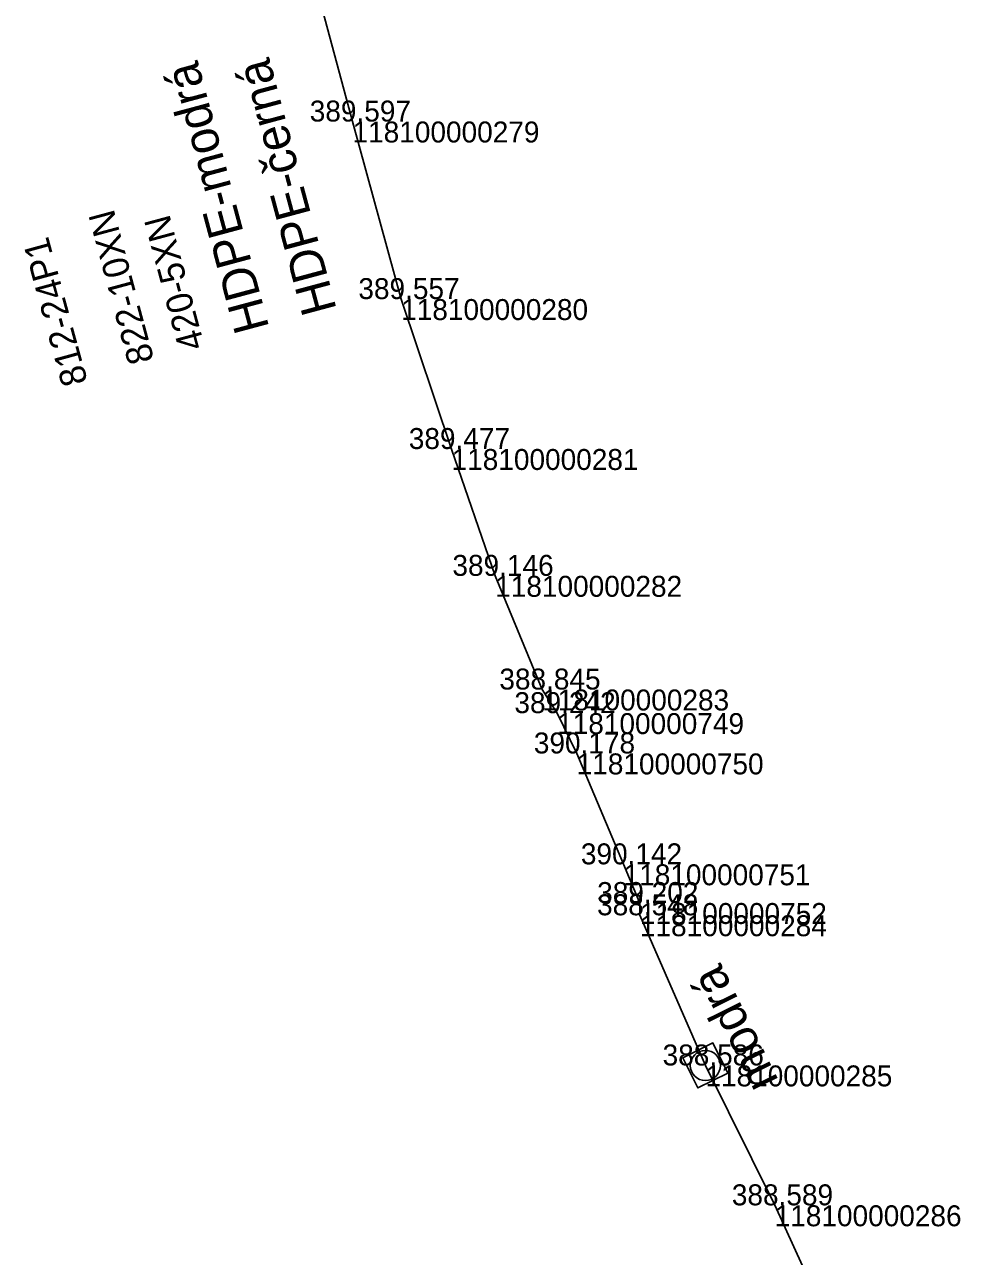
# Model space of a CAD drawing. Extents: x -724084 to -720954, y -948423 to -945131.
# Drawn here: x -721947.4 to -721893.7, y -947598.7 to -947528.1 of the extents above; entities that cross this region are included whole.
import ezdxf

# ---------------------------------------------------------------- set-up
doc = ezdxf.new("R2010")
doc.units = 0
for name, color, linetype in [('Vrstva 28', 7, 'Continuous'), ('Vrstva 31', 7, 'Continuous'), ('Vrstva 33', 7, 'Continuous'), ('Vrstva 60', 7, 'Continuous'), ('Vrstva 61', 7, 'Continuous')]:
    doc.layers.add(name, color=color, linetype=linetype)

msp = doc.modelspace()

# ---------------------------------------------------------------- linework, layer by layer
at = {"layer": 'Vrstva 28'}
for points in [[(-721916.845, -947567.574), (-721917.7, -947566.221), (-721920.393, -947559.707), (-721922.892, -947552.44), (-721925.781, -947543.85), (-721928.567, -947533.677), (-721931.184, -947523.941), (-721933.084, -947514.601), (-721934.922, -947507.209), (-721935.577, -947505.11), (-721937.863, -947494.901), (-721938.161, -947492.286)], [(-721916.845, -947567.574), (-721915.725, -947569.883), (-721913.037, -947576.236), (-721912.103, -947578.454)], [(-721901.7, -947601.624), (-721904.382, -947595.773), (-721908.35, -947587.759), (-721912.103, -947579.155), (-721912.103, -947578.454)]]:
    msp.add_lwpolyline(points, dxfattribs=at)
at = {"layer": 'Vrstva 31'}
for points in [[(-721916.845, -947567.574), (-721917.7, -947566.221), (-721920.393, -947559.707), (-721922.892, -947552.44), (-721925.781, -947543.85), (-721928.567, -947533.677), (-721931.184, -947523.941), (-721933.084, -947514.601), (-721934.922, -947507.209), (-721935.577, -947505.11), (-721937.863, -947494.901), (-721938.161, -947492.286)], [(-721912.103, -947578.454), (-721913.037, -947576.236), (-721915.725, -947569.883), (-721916.845, -947567.574)], [(-721901.7, -947601.624), (-721904.382, -947595.773), (-721908.35, -947587.759), (-721912.103, -947579.155), (-721912.103, -947578.454)]]:
    msp.add_lwpolyline(points, dxfattribs=at)
at = {"layer": 'Vrstva 33'}
msp.add_lwpolyline([(-721901.7, -947601.624), (-721904.382, -947595.773), (-721908.35, -947587.759), (-721912.103, -947579.155), (-721912.103, -947578.454), (-721913.037, -947576.236), (-721915.725, -947569.883), (-721916.845, -947567.574), (-721917.7, -947566.221), (-721920.393, -947559.707), (-721922.892, -947552.44), (-721925.781, -947543.85), (-721928.567, -947533.677), (-721931.184, -947523.941)], dxfattribs=at)
msp.add_lwpolyline([(-721907.064, -947588.193), (-721907.916, -947586.473), (-721909.636, -947587.325), (-721908.784, -947589.045)], close=True, dxfattribs=at)
msp.add_circle((-721908.35, -947587.759), 0.864, dxfattribs=at)
at = {"layer": 'Vrstva 60'}
for p, q in [((-721928.567, -947533.677), (-721928.567, -947533.677)), ((-721925.781, -947543.85), (-721925.781, -947543.85)), ((-721922.892, -947552.44), (-721922.892, -947552.44)), ((-721920.393, -947559.707), (-721920.393, -947559.707)), ((-721917.7, -947566.221), (-721917.7, -947566.221)), ((-721916.845, -947567.574), (-721916.845, -947567.574)), ((-721915.725, -947569.883), (-721915.725, -947569.883)), ((-721913.037, -947576.236), (-721913.037, -947576.236)), ((-721912.103, -947578.454), (-721912.103, -947578.454)), ((-721912.103, -947579.155), (-721912.103, -947579.155)), ((-721908.35, -947587.759), (-721908.35, -947587.759)), ((-721904.382, -947595.773), (-721904.382, -947595.773))]:
    msp.add_line(p, q, dxfattribs=at)

# ---------------------------------------------------------------- texts
at = {"layer": 'Vrstva 28'}
msp.add_text('812-24P1', height=1.5, rotation=105.31563, dxfattribs=at).set_placement((-721943.723, -947548.595))
at = {"layer": 'Vrstva 31'}
for s, p in [('822-10XN', (-721939.922, -947547.347)), ('420-5XN', (-721937.024, -947546.568))]:
    msp.add_text(s, height=1.5, rotation=105.04527, dxfattribs=at).set_placement(p)
at = {"layer": 'Vrstva 33'}
for s, rotation, p in [('HDPE-modrá', 105.04527, (-721933.329, -947545.489)), ('HDPE-černá', 105.04527, (-721929.466, -947544.451)), ('modrá', 116.34155, (-721904.134, -947588.635))]:
    msp.add_text(s, height=2, rotation=rotation, dxfattribs=at).set_placement(p)
at = {"layer": 'Vrstva 60'}
for s, p in [('118100000279', (-721928.567, -947534.877)), ('118100000280', (-721925.781, -947545.05)), ('118100000281', (-721922.892, -947553.64)), ('118100000282', (-721920.393, -947560.907)), ('118100000283', (-721917.7, -947567.421)), ('118100000749', (-721916.845, -947568.774)), ('118100000750', (-721915.725, -947571.083)), ('118100000751', (-721913.037, -947577.436)), ('118100000752', (-721912.103, -947579.654)), ('118100000284', (-721912.103, -947580.355)), ('118100000285', (-721908.35, -947588.959)), ('118100000286', (-721904.382, -947596.973))]:
    msp.add_text(s, height=1.2, dxfattribs=at).set_placement(p)
at = {"layer": 'Vrstva 61'}
for s, p in [('389.597', (-721931.019, -947533.677)), ('389.557', (-721928.233, -947543.85)), ('389.477', (-721925.344, -947552.44)), ('389.146', (-721922.845, -947559.707)), ('388.845', (-721920.156, -947566.221)), ('389.242', (-721919.293, -947567.574)), ('390.178', (-721918.179, -947569.883)), ('390.142', (-721915.485, -947576.236)), ('389.202', (-721914.551, -947578.454)), ('388.548', (-721914.557, -947579.155)), ('388.586', (-721910.802, -947587.759)), ('388.589', (-721906.836, -947595.773))]:
    msp.add_text(s, height=1.2, dxfattribs=at).set_placement(p)

doc.saveas('drawing.dxf')
